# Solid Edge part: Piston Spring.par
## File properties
Title: Piston Spring
Author: Dan
Template: Normal.par
Last saved by: Dan
Revision: 29
Application: Solid Edge
Density: 0.0000078 kg/mm^3
Accuracy: 0.01
Document Number: P52-015
Project Name: Piston Pump P52
Material: steel
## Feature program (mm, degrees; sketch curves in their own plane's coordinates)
helix protrusion "HelixProtrusion_1"  NumberOfTurns = 16
helix protrusion "HelixProtrusion_2"  Pitch = 1.85 mm; NumberOfTurns = 1
helix protrusion "HelixProtrusion_3"  Pitch = 1.85 mm; NumberOfTurns = 1
sketch for "unnamed RevolvedCutout 1" plane through (0, 0, 0) normal (0, 0, 1) x-axis (1, 0, 0)
  line (-24.79, 0) -> (-24.79, 8.7552)
revolve "unnamed RevolvedCutout 1" cut full turn 360 deg
sketch for "unnamed RevolvedCutout 2" plane through (0, 0, 0) normal (0, 0, 1) x-axis (1, 0, 0)
  line (52.01, 0) -> (52.01, 10.4347)
revolve "unnamed RevolvedCutout 2" cut full turn 360 deg
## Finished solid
Body 1: solid body, 5 faces, 4 edges, 2 vertices.
  Faces by surface: spline 3, plane 2
  Edges by curve: circle 2, intersection 2
Bounding box of the edges (mm; curved faces can reach further): 76.800 x 13.864 x 14.088, from (-24.79, -6.9324, -7.0385) to (52.01, 6.9321, 7.05).
Planar faces by outward normal: +x 1, -x 1
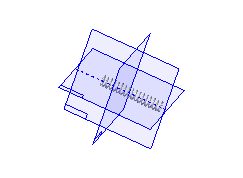
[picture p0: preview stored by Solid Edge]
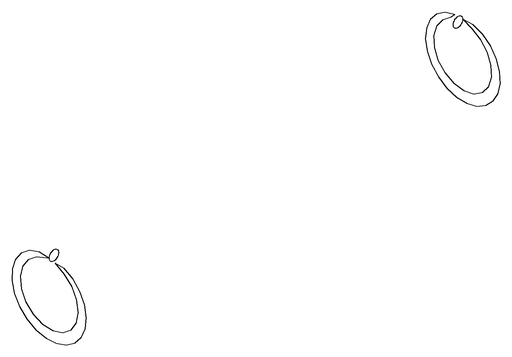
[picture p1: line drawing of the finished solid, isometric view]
